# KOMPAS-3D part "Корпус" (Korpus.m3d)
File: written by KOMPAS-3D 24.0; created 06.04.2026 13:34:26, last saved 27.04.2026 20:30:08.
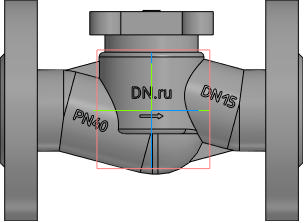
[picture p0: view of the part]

Document properties: Автор: R2D2; Полное имя файла: C:\Работа\ГОТОВЫЕ ИСХОДНИКИ\VSO2130M-F-S Клапан запорный сальниковый DN.ru Ду15-100 Ру40\исходные материалы\DN15\Korpus.m3d

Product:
- Body: Труба / Нестандартная труба / L = 70.4 мм  | qty 1  | 2 such rows
    Материал: Нестандартная труба (density 7856 kg/m3)
    Масса: 2.685704
    Раздел спецификации: Детали
    Примечание: 0,53 кг
    additional columns: Pipeline; 0.035; 0; 0; 0.002; 0.07035; true; 0.04
- Body: Тело 4  | qty 1
    Материал: Нестандартная труба (density 7856 kg/m3)
    Масса: 2.685704
- Body: Тело 5  | qty 1
    Материал: Нестандартная труба (density 7856 kg/m3)
    Масса: 2.685704
- Body: Тело 8  | qty 1
    Материал: Нестандартная труба (density 7856 kg/m3)
    Масса: 2.685704
- Body: Тело 10  | qty 1
    Материал: Нестандартная труба (density 7856 kg/m3)
    Масса: 2.685704
- Body: Тело 11  | qty 1
    Материал: Нестандартная труба (density 7856 kg/m3)
    Масса: 2.685704
- Body: Тело 12  | qty 1
    Материал: Нестандартная труба (density 7856 kg/m3)
    Масса: 2.685704
- Body: Тело 13  | qty 1
    Материал: Нестандартная труба (density 7856 kg/m3)
    Масса: 2.685704
- Part/product: Корпус
    Масса: 6.9

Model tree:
1. Труба:1  (labels: {F703FF30-5BE6-4673-A7F1-8EDA1BE1E2D1}; SHAPEOBJECT3D_ATTR_BUTT; SHAPEOBJECT3D_ATTR_VALID; SHAPEOBJECT3D_ATTR_BUTT_AREA)
     PIPE_R = 3
2. Труба:2  (labels: {F703FF30-5BE6-4673-A7F1-8EDA1BE1E2D1}; SHAPEOBJECT3D_ATTR_BUTT; SHAPEOBJECT3D_ATTR_VALID; SHAPEOBJECT3D_ATTR_BUTT_AREA)
     PIPE_R = 3
3. Колонна
4. Элемент выдавливания:1
     Смещение 1 = -1; Смещение 2 = -5
5. Скругление:17  (with: Ребро.Элемент выдавливания:1)
     Радиус = 2
6. Скругление:18  (with: Ребро.Элемент выдавливания:1)
7. Скругление:24
     Радиус = 1.5
8. Элемент выдавливания:2
     Расстояние 1 = 6
9. Эскиз:4  (with: Грань.Элемент выдавливания:1)
10. Элемент выдавливания:3
     Расстояние 1 = 7.5; Смещение 1 = 2.15637
11. ОТЛИВКА
12. Скругление:6  (with: Грань.Элемент выдавливания:1)
     Радиус = 2
13. Элемент выдавливания:6  (with: Грань.Элемент выдавливания:1)
     Смещение 1 = 4
14. ЛЕЙБЛ
15. Элемент выдавливания:7  (with: Грань.Элемент выдавливания:1)
     Расстояние 1 = 23.479; Смещение 1 = 1
16. Dn
17. Pn
18. Стрелочка
19. Элемент выдавливания:10  (with: Грань.Труба:1)
     Расстояние 1 = 18.1253; Смещение 1 = 1
20. Элемент выдавливания:11  (with: Грань.Труба:2)
     Расстояние 1 = 18.4585; Смещение 1 = 1
21. Элемент выдавливания:12  (with: Грань.Элемент выдавливания:1)
     Расстояние 1 = 23.4999; Смещение 1 = 1
22. Материал
23. Элемент выдавливания:13  (with: Грань.Элемент выдавливания:1)
     Расстояние 1 = 22.9941; Смещение 1 = 0.5
24. Фланец верх  (with: Грань.Элемент выдавливания:3)
25. Элемент выдавливания:14
     Расстояние 1 = 10
26. Эскиз:18  (with: Грань.Элемент выдавливания:14)
27. Элемент выдавливания:15
     Расстояние 1 = 0.5
28. Эскиз:19  (with: Грань.Элемент выдавливания:14, Ребро.Элемент выдавливания:14)
29. Элемент выдавливания:16  (with: Грань.Элемент выдавливания:14)
     Расстояние 1 = 0.5; Расстояние 2 = 11; Смещение 2 = 1
30. Массив по сетке:1  (with: Элемент выдавливания:16, Эскиз:19)  (4 pattern instances)
     Угол раствора = 90
31. Фланец
32. Элемент вращения:1
     Угол 1 = 360
33. отвертие во фланце  (with: Грань.Элемент вращения:1)
34. Элемент выдавливания:8
35. Массив по концентрической сетке:2  (with: Элемент выдавливания:8, Эскиз:10, Грань.Элемент вращения:1)  (4 pattern instances)
     Шаг 2 = 360
36. Зеркальный массив:1
37. Экземпляр ( 1 )
38. Экземпляр ( 2 )  (with: Элемент вращения:1, Массив по концентрической сетке:2, Экземпляр ( 1 ), Элемент выдавливания:8)
39. Экземпляр ( 3 )  (with: Элемент выдавливания:8)
40. Экземпляр ( 4 )  (with: Элемент выдавливания:8)

Expressions: DS/2+3; DN/2; LL/2; D2/2-3; D2-3*2; D1/2
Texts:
  GOST 26.020 Pr3
  var3D
  GS-C25
  смещение колонны вниз
  LL-10
  DN+20
  DS+5
  Труба / Нестандартная труба / L = %s мм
